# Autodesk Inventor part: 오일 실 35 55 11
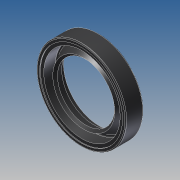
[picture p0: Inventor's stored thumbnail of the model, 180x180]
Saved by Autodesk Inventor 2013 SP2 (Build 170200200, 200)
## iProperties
Created: 2025-06
Part Number: 오일 실 35 55 11
Material: Generic
Document SubType Name: Modeling
Designer: i
Density: 1 g/cm^3
Author: i
변환 표준: STEP AP214IS
전처리기: Build: 200, Release: 2013 SP2 Update 6 - Date: Thu 07/17/2014
전송 단위: 밀리미터
불확실성: 0.01
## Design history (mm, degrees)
node "오일 실 35 55 111"
body "Solid1"
node "기준1"
